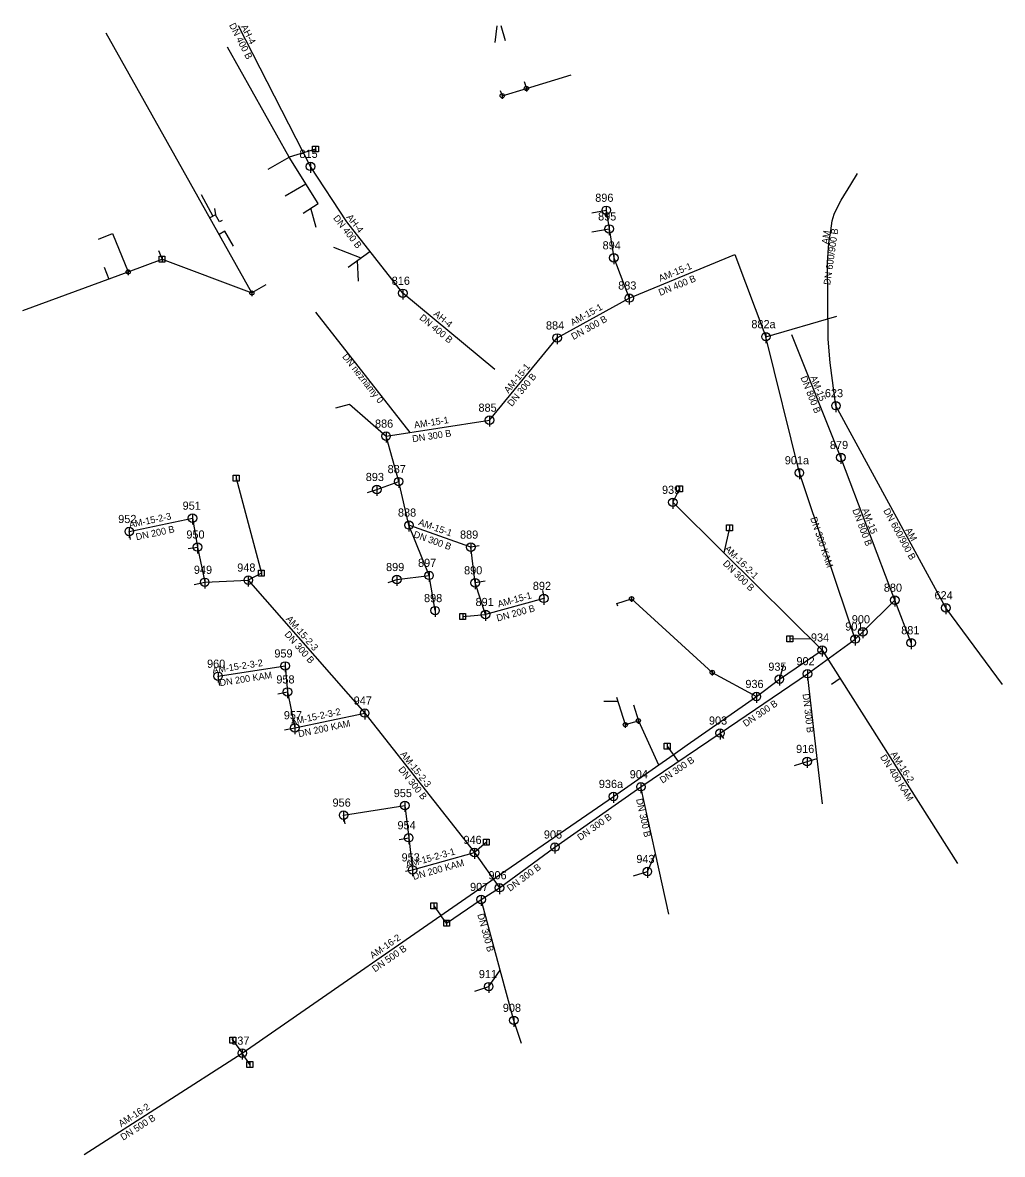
# Model space of a CAD drawing. Extents: x -492400 to -492169, y -1127087 to -1126820.
import ezdxf

# ---------------------------------------------------------------- set-up
doc = ezdxf.new("R2010")
doc.units = 0
for name, color, linetype in [('_pripojka_kanal_destova_priblizne_', 7, 'Continuous'), ('_pripojka_kanal_jednotna_prevzato_z_dokumentace_', 7, 'Continuous'), ('_pripojka_kanal_jednotna_priblizne_', 7, 'Continuous'), ('_pripojka_kanal_splaskova_priblizne_', 7, 'Continuous'), ('_stoka_jednotna_smvak_prevzato_z_dokumentace_', 7, 'Continuous'), ('_stoka_jednotna_smvak_priblizne_', 7, 'Continuous'), ('Default', 7, 'Continuous'), ('MoLevel 1', 7, 'Continuous'), ('MoLevel 119', 7, 'Continuous'), ('MoLevel 120', 7, 'Continuous'), ('MoLevel 2', 7, 'Continuous'), ('MoLevel 57', 7, 'Continuous'), ('MoLevel 60', 7, 'Continuous'), ('MoLevel 63', 7, 'Continuous'), ('MoLevel 68', 7, 'Continuous'), ('MoLevel 69', 7, 'Continuous')]:
    doc.layers.add(name, color=color, linetype=linetype)

# ---------------------------------------------------------------- blocks, each defined once
blk = doc.blocks.new('_vpust_')
at = {"layer": 'Default'}
blk.add_line((0, 0.000025), (0, -0.000025), dxfattribs=at)
blk.add_lwpolyline([(-0.000035, 0.000035), (0.000035, 0.000035), (0.000035, -0.000035), (-0.000035, -0.000035), (-0.000035, 0.000035)], dxfattribs=at)
blk = doc.blocks.new('_sachta_kanal_prip_')
at = {"layer": 'Default'}
blk.add_line((0, 0.00005), (0, -0.000075), dxfattribs=at)
blk.add_circle((0, 0), 0.00005, dxfattribs=at)
blk = doc.blocks.new('_sachta_kanal_prevzato_z_dokumentace_')
at = {"layer": 'Default'}
blk.add_line((0, 0.00005), (0, -0.000075), dxfattribs=at)
blk.add_circle((0, 0), 0.00005, dxfattribs=at)

msp = doc.modelspace()

# ---------------------------------------------------------------- linework, layer by layer
at = {"layer": '_pripojka_kanal_destova_priblizne_'}
for p, q in [((-492345.92, -1126883.53), (-492380.35, -1126822.11)), ((-492288.43, -1126824.33), (-492288, -1126820.38)), ((-492342.1, -1126854.29), (-492337.11, -1126851.45)), ((-492330.86, -1126849.51), (-492337.11, -1126851.45)), ((-492338.06, -1126860.58), (-492333.15, -1126857.76)), ((-492357.85, -1126860.28), (-492355.15, -1126865.41)), ((-492353.53, -1126866.74), (-492354.49, -1126865.04)), ((-492330.74, -1126868.06), (-492332.01, -1126863.53)), ((-492352.9, -1126866.39), (-492353.53, -1126866.74)), ((-492326.6, -1126872.68), (-492320.16, -1126875.26)), ((-492375.13, -1126878.56), (-492367.14, -1126875.52)), ((-492367.95, -1126873.53), (-492367.14, -1126875.52)), ((-492367.14, -1126875.52), (-492345.92, -1126883.53)), ((-492323.14, -1126877.45), (-492318.02, -1126873.7)), ((-492380.81, -1126877.47), (-492379.72, -1126880.25)), ((-492320.73, -1126880.78), (-492320.95, -1126875.84)), ((-492400.05, -1126887.71), (-492375.13, -1126878.56)), ((-492342.59, -1126881.61), (-492345.92, -1126883.53)), ((-492349.62, -1126927.31), (-492343.67, -1126949.76)), ((-492244.91, -1126929.83), (-492246.47, -1126933.01)), ((-492233.11, -1126939.05), (-492234.4, -1126944.95)), ((-492343.67, -1126949.76), (-492346.75, -1126951.39)), ((-492256.22, -1126955.79), (-492237.18, -1126973.21)), ((-492296.12, -1126959.98), (-492290.74, -1126959.51)), ((-492218.82, -1126965.25), (-492213.92, -1126965.22)), ((-492220.38, -1126971.34), (-492221.32, -1126974.81)), ((-492237.18, -1126973.21), (-492226.74, -1126978.9)), ((-492262.81, -1126980.03), (-492259.45, -1126980.04)), ((-492234.44, -1126988.81), (-492235.34, -1126987.54)), ((-492247.81, -1126990.64), (-492245.25, -1126994.28)), ((-492290.53, -1127013.33), (-492293.33, -1127015.75)), ((-492299.91, -1127032.48), (-492291.76, -1127026.86)), ((-492302.92, -1127028.36), (-492301.25, -1127030.63)), ((-492299.91, -1127032.48), (-492301.25, -1127030.63)), ((-492350.41, -1127060.13), (-492348.18, -1127063.19)), ((-492346.42, -1127065.89), (-492348.18, -1127063.19))]:
    msp.add_line(p, q, dxfattribs=at)
for points in [[(-492354.72, -1126863.58), (-492354.49, -1126865.04), (-492355.86, -1126865.8)], [(-492382.13, -1126870.8), (-492378.83, -1126869.49), (-492375.13, -1126878.56)], [(-492350.26, -1126872.5), (-492352.28, -1126868.94), (-492353.67, -1126869.7)], [(-492259.51, -1126957.55), (-492259.7, -1126956.95), (-492256.22, -1126955.79)]]:
    msp.add_lwpolyline(points, dxfattribs=at)
at = {"layer": '_pripojka_kanal_jednotna_prevzato_z_dokumentace_'}
for p, q in [((-492265.61, -1126864.62), (-492262.2, -1126863.99)), ((-492265.62, -1126869.1), (-492261.53, -1126868.4)), ((-492318.59, -1126930.71), (-492316.4, -1126929.98)), ((-492374.55, -1126941.78), (-492374.87, -1126939.91)), ((-492360.97, -1126943.93), (-492358.77, -1126943.57)), ((-492292.22, -1126943.28), (-492294.19, -1126943.6)), ((-492359.55, -1126952.39), (-492357.04, -1126951.91)), ((-492313.71, -1126951.95), (-492311.66, -1126951.26)), ((-492290.82, -1126951.64), (-492293.18, -1126952.04)), ((-492277.23, -1126953.82), (-492276.89, -1126955.75)), ((-492353.5, -1126976.27), (-492353.89, -1126974.11)), ((-492339.77, -1126978.24), (-492337.51, -1126977.82)), ((-492338.23, -1126986.75), (-492335.75, -1126986.29)), ((-492217.71, -1126995.22), (-492214.76, -1126994.25)), ((-492323.89, -1127008.99), (-492324.25, -1127006.93)), ((-492311.1, -1127012.7), (-492308.86, -1127012.28)), ((-492309.59, -1127020.14), (-492307.94, -1127019.88)), ((-492255.77, -1127021.31), (-492252.49, -1127020.25)), ((-492293.24, -1127048.54), (-492289.97, -1127047.45))]:
    msp.add_line(p, q, dxfattribs=at)
at = {"layer": '_pripojka_kanal_jednotna_priblizne_'}
for p, q in [((-492285.97, -1126823.95), (-492287.02, -1126820.38)), ((-492337.11, -1126851.45), (-492351.7, -1126825.46)), ((-492281.06, -1126835.2), (-492270.5, -1126831.98)), ((-492286.77, -1126836.93), (-492281.06, -1126835.2)), ((-492281.59, -1126833.58), (-492281.06, -1126835.2)), ((-492287.25, -1126835.68), (-492286.77, -1126836.93)), ((-492330.23, -1126862.41), (-492337.11, -1126851.45)), ((-492333.79, -1126864.66), (-492330.23, -1126862.41)), ((-492326.05, -1126910.67), (-492322.88, -1126909.84)), ((-492259.76, -1126979.07), (-492257.71, -1126985.55)), ((-492257.71, -1126985.55), (-492254.63, -1126984.63)), ((-492254.63, -1126984.63), (-492249.84, -1126995.05))]:
    msp.add_line(p, q, dxfattribs=at)
at = {"layer": '_pripojka_kanal_splaskova_priblizne_'}
for p, q in [((-492330.91, -1126888.04), (-492308.63, -1126916.51)), ((-492208.99, -1126975.99), (-492206.98, -1126974.58)), ((-492255.78, -1126980.85), (-492254.63, -1126984.63))]:
    msp.add_line(p, q, dxfattribs=at)
at = {"layer": '_stoka_jednotna_smvak_prevzato_z_dokumentace_'}
for p, q in [((-492332.06, -1126853.61), (-492349.05, -1126820.38)), ((-492262.2, -1126863.99), (-492261.53, -1126868.4)), ((-492261.53, -1126868.4), (-492260.41, -1126875.23)), ((-492260.41, -1126875.23), (-492256.77, -1126884.73)), ((-492256.77, -1126884.73), (-492231.86, -1126874.46)), ((-492273.79, -1126894.16), (-492256.77, -1126884.73)), ((-492289.78, -1126913.6), (-492273.79, -1126894.16)), ((-492216.6, -1126926.03), (-492224.49, -1126893.86)), ((-492206.81, -1126922.42), (-492218.35, -1126893.4)), ((-492182.01, -1126957.94), (-492207.96, -1126910.17)), ((-492314.22, -1126917.37), (-492289.78, -1126913.6)), ((-492311.24, -1126928.11), (-492314.22, -1126917.37)), ((-492194.04, -1126956.14), (-492206.81, -1126922.42)), ((-492203.42, -1126965.32), (-492216.6, -1126926.03)), ((-492316.4, -1126929.98), (-492311.24, -1126928.11)), ((-492308.8, -1126938.39), (-492311.24, -1126928.11)), ((-492374.87, -1126939.91), (-492359.93, -1126936.76)), ((-492359.93, -1126936.76), (-492358.77, -1126943.57)), ((-492294.19, -1126943.6), (-492308.8, -1126938.39)), ((-492304.06, -1126950.27), (-492308.8, -1126938.39)), ((-492358.77, -1126943.57), (-492357.04, -1126951.91)), ((-492293.18, -1126952.04), (-492294.19, -1126943.6)), ((-492311.66, -1126951.26), (-492304.06, -1126950.27)), ((-492302.64, -1126958.6), (-492304.06, -1126950.27)), ((-492357.04, -1126951.91), (-492346.75, -1126951.39)), ((-492346.75, -1126951.39), (-492319.26, -1126982.82)), ((-492290.74, -1126959.52), (-492293.18, -1126952.04)), ((-492276.94, -1126955.72), (-492290.74, -1126959.52)), ((-492201.6, -1126963.61), (-492194.04, -1126956.14)), ((-492190.2, -1126966.19), (-492194.04, -1126956.14)), ((-492168.65, -1126976.03), (-492182.01, -1126957.94)), ((-492203.42, -1126965.32), (-492201.6, -1126963.61)), ((-492214.68, -1126973.51), (-492203.42, -1126965.32)), ((-492221.32, -1126974.81), (-492211.2, -1126967.91)), ((-492211.2, -1126967.91), (-492179.25, -1127018.37)), ((-492353.89, -1126974.11), (-492338.04, -1126971.68)), ((-492338.04, -1126971.68), (-492337.51, -1126977.82)), ((-492235.34, -1126987.54), (-492214.68, -1126973.51)), ((-492212.39, -1126993.52), (-492214.68, -1126973.51)), ((-492226.74, -1126978.9), (-492221.32, -1126974.81)), ((-492337.51, -1126977.82), (-492335.75, -1126986.29)), ((-492243.1, -1126990.34), (-492226.74, -1126978.9)), ((-492335.75, -1126986.29), (-492319.26, -1126982.82)), ((-492319.26, -1126982.82), (-492293.33, -1127015.75)), ((-492254.01, -1127000.23), (-492235.34, -1126987.54)), ((-492246.43, -1126992.67), (-492243.1, -1126990.34)), ((-492260.52, -1127002.52), (-492246.43, -1126992.67)), ((-492214.76, -1126994.25), (-492212.39, -1126993.52)), ((-492211.17, -1127004.23), (-492212.39, -1126993.52)), ((-492274.33, -1127014.47), (-492254.01, -1127000.23)), ((-492250.54, -1127016.01), (-492254.01, -1127000.23)), ((-492324.25, -1127006.93), (-492309.79, -1127004.67)), ((-492309.79, -1127004.67), (-492308.86, -1127012.28)), ((-492308.86, -1127012.28), (-492307.94, -1127019.88)), ((-492287.43, -1127024.09), (-492274.33, -1127014.47)), ((-492307.94, -1127019.88), (-492293.33, -1127015.75)), ((-492293.33, -1127015.75), (-492287.43, -1127024.09)), ((-492252.49, -1127020.25), (-492250.54, -1127016.01)), ((-492247.4, -1127030.36), (-492250.54, -1127016.01)), ((-492291.76, -1127026.86), (-492287.43, -1127024.09)), ((-492287.24, -1127043.56), (-492291.76, -1127026.86)), ((-492289.97, -1127047.45), (-492287.25, -1127043.57)), ((-492284.03, -1127055.43), (-492287.24, -1127043.56)), ((-492282.24, -1127060.93), (-492284.03, -1127055.43)), ((-492385.56, -1127087.1), (-492348.18, -1127063.19))]:
    msp.add_line(p, q, dxfattribs=at)
for points in [[(-492310.26, -1126883.61), (-492323.46, -1126866.73), (-492332.06, -1126853.61)], [(-492246.47, -1126933.01), (-492234.4, -1126944.95), (-492211.2, -1126967.91)], [(-492348.18, -1127063.19), (-492288.46, -1127021.76), (-492260.52, -1127002.52)]]:
    msp.add_lwpolyline(points, dxfattribs=at)
at = {"layer": '_stoka_jednotna_smvak_priblizne_'}
for p, q in [((-492231.86, -1126874.46), (-492224.49, -1126893.86)), ((-492288.5, -1126901.6), (-492310.26, -1126883.61)), ((-492224.49, -1126893.86), (-492207.77, -1126888.98)), ((-492322.88, -1126909.84), (-492314.22, -1126917.37))]:
    msp.add_line(p, q, dxfattribs=at)
msp.add_lwpolyline([(-492207.96, -1126910.17), (-492209.3, -1126900.01), (-492209.77, -1126894.44), (-492209.94, -1126876.36), (-492209.61, -1126871.75), (-492209.19, -1126868.85), (-492208.87, -1126866.47), (-492208.35, -1126864.92), (-492208, -1126864.02), (-492206.71, -1126861.61), (-492204.45, -1126857.92), (-492202.88, -1126855.26)], dxfattribs=at)

# ---------------------------------------------------------------- block references
at = {"layer": 'MoLevel 119', "xscale": 20000, "yscale": 20000}
for p in [(-492332.06, -1126853.61), (-492262.2, -1126863.99), (-492261.53, -1126868.4), (-492260.41, -1126875.23), (-492310.26, -1126883.61), (-492256.77, -1126884.73), (-492273.79, -1126894.16), (-492224.49, -1126893.86), (-492207.96, -1126910.17), (-492289.78, -1126913.6), (-492314.22, -1126917.37), (-492206.81, -1126922.42), (-492216.6, -1126926.03), (-492316.4, -1126929.98), (-492311.24, -1126928.11), (-492246.47, -1126933.01), (-492359.93, -1126936.76), (-492374.87, -1126939.91), (-492308.8, -1126938.39), (-492358.77, -1126943.57), (-492294.19, -1126943.6), (-492346.75, -1126951.39), (-492311.66, -1126951.26), (-492304.06, -1126950.27), (-492357.04, -1126951.91), (-492293.18, -1126952.04), (-492276.94, -1126955.72), (-492194.04, -1126956.14), (-492302.64, -1126958.6), (-492290.74, -1126959.52), (-492182.01, -1126957.94), (-492201.6, -1126963.61), (-492203.42, -1126965.32), (-492190.2, -1126966.19), (-492211.2, -1126967.91), (-492338.04, -1126971.68), (-492353.89, -1126974.11), (-492221.32, -1126974.81), (-492214.68, -1126973.51), (-492337.51, -1126977.82), (-492226.74, -1126978.9), (-492319.26, -1126982.82), (-492335.75, -1126986.29), (-492235.34, -1126987.54), (-492214.76, -1126994.25), (-492254.01, -1127000.23), (-492309.79, -1127004.67), (-492260.52, -1127002.52), (-492324.25, -1127006.93), (-492308.86, -1127012.28), (-492293.33, -1127015.75), (-492274.33, -1127014.47), (-492307.94, -1127019.88), (-492252.49, -1127020.25), (-492287.43, -1127024.09), (-492291.76, -1127026.86), (-492289.97, -1127047.45), (-492284.03, -1127055.43), (-492348.18, -1127063.19)]:
    msp.add_blockref('_sachta_kanal_prevzato_z_dokumentace_', p, dxfattribs=at)
at = {"layer": 'MoLevel 57', "xscale": 10000, "yscale": 10000}
for p in [(-492281.06, -1126835.2), (-492286.77, -1126836.93), (-492375.13, -1126878.56), (-492345.92, -1126883.53), (-492256.22, -1126955.79), (-492237.18, -1126973.21), (-492257.71, -1126985.55), (-492254.63, -1126984.63)]:
    msp.add_blockref('_sachta_kanal_prip_', p, dxfattribs=at)
at = {"layer": 'MoLevel 63', "xscale": 20000, "yscale": 20000}
for p in [(-492330.86, -1126849.51), (-492367.14, -1126875.52), (-492349.62, -1126927.31), (-492244.91, -1126929.83), (-492233.11, -1126939.05), (-492343.67, -1126949.76), (-492296.12, -1126959.98), (-492218.82, -1126965.25), (-492247.81, -1126990.64), (-492290.53, -1127013.33), (-492302.92, -1127028.36), (-492299.91, -1127032.48), (-492350.41, -1127060.13), (-492346.42, -1127065.89)]:
    msp.add_blockref('_vpust_', p, dxfattribs=at)

# ---------------------------------------------------------------- texts
at = {"layer": 'MoLevel 1'}
for s, height, rotation, p in [('DN 600/900 B', 1.6049, 81.7674, (-492209.32, -1126881.74)), ('DN 400 B', 1.605, 320.4161, (-492306.48, -1126889.62))]:
    msp.add_text(s, height=height, rotation=rotation, dxfattribs=at).set_placement(p)
at = {"layer": 'MoLevel 120'}
for s, p in [('815', (-492334.67, -1126851.61)), ('896', (-492264.81, -1126861.99)), ('895', (-492264.14, -1126866.4)), ('894', (-492263.07, -1126873.23)), ('816', (-492312.88, -1126881.61)), ('883', (-492259.39, -1126882.73)), ('884', (-492276.45, -1126892.16)), ('882a', (-492227.93, -1126891.86)), ('623', (-492210.57, -1126908.17)), ('885', (-492292.39, -1126911.6)), ('886', (-492316.83, -1126915.37)), ('879', (-492209.38, -1126920.42)), ('901a', (-492220.04, -1126924.03)), ('893', (-492319.01, -1126927.98)), ('887', (-492313.85, -1126926.11)), ('939', (-492249.04, -1126931.01)), ('951', (-492362.27, -1126934.76)), ('888', (-492311.41, -1126936.39)), ('952', (-492377.48, -1126937.91)), ('950', (-492361.38, -1126941.57)), ('889', (-492296.75, -1126941.6)), ('949', (-492359.61, -1126949.91)), ('948', (-492349.37, -1126949.39)), ('899', (-492314.22, -1126949.26)), ('897', (-492306.67, -1126948.27)), ('890', (-492295.79, -1126950.04)), ('892', (-492279.55, -1126953.72)), ('880', (-492196.65, -1126954.14)), ('898', (-492305.25, -1126956.6)), ('891', (-492293.08, -1126957.52)), ('624', (-492184.67, -1126955.94)), ('900', (-492204.21, -1126961.61)), ('934', (-492213.86, -1126965.91)), ('901', (-492205.76, -1126963.32)), ('881', (-492192.54, -1126964.19)), ('959', (-492340.6, -1126969.68)), ('960', (-492356.5, -1126972.11)), ('935', (-492223.93, -1126972.81)), ('902', (-492217.29, -1126971.51)), ('958', (-492340.13, -1126975.82)), ('936', (-492229.35, -1126976.9)), ('947', (-492321.87, -1126980.82)), ('957', (-492338.36, -1126984.29)), ('903', (-492237.95, -1126985.54)), ('916', (-492217.37, -1126992.25)), ('936a', (-492263.96, -1127000.52)), ('904', (-492256.67, -1126998.23)), ('955', (-492312.41, -1127002.67)), ('956', (-492326.86, -1127004.93)), ('954', (-492311.52, -1127010.28)), ('946', (-492295.94, -1127013.75)), ('905', (-492276.94, -1127012.47)), ('953', (-492310.55, -1127017.88)), ('943', (-492255.1, -1127018.25)), ('906', (-492290.04, -1127022.09)), ('907', (-492294.38, -1127024.86)), ('911', (-492292.3, -1127045.45)), ('908', (-492286.64, -1127053.43)), ('937', (-492350.79, -1127061.19))]:
    msp.add_text(s, height=1.926, dxfattribs=at).set_placement(p)
at = {"layer": 'MoLevel 2'}
for s, rotation, p in [('AM', 81.7674, (-492209.78, -1126872.08)), ('AH-4', 320.4161, (-492303.13, -1126888.71)), ('AH-4', 320.4161, (-492303.13, -1126888.71)), ('AH-4', 320.4161, (-492303.13, -1126888.71))]:
    msp.add_text(s, height=1.605, rotation=rotation, dxfattribs=at).set_placement(p)
at = {"layer": 'MoLevel 60'}
msp.add_text('DN neznámý 0', height=1.6049, rotation=308.0485, dxfattribs=at).set_placement((-492324.67, -1126898.62))
at = {"layer": 'MoLevel 68'}
for s, height, rotation, p in [('DN 400 B', 1.605, 297.0916, (-492351.35, -1126820.22)), ('DN 400 B', 1.605, 308.0267, (-492326.8, -1126865.87)), ('DN 400 B', 1.605, 22.4237, (-492249.46, -1126884.25)), ('DN 300 B', 1.605, 28.9931, (-492269.95, -1126894.67)), ('DN 300 B', 1.605, 50.5556, (-492284.5, -1126910.51)), ('DN 800 B', 1.605, 291.6897, (-492216.37, -1126903.52)), ('DN 300 B', 1.605, 8.7782, (-492307.91, -1126918.82)), ('DN 800 B', 1.605, 290.7454, (-492204.13, -1126934.82)), ('DN 600/900 B', 1.6049, 298.512, (-492196.83, -1126934.96)), ('DN 300 KAM', 1.605, 288.5501, (-492214.05, -1126936.76)), ('DN 200 B', 1.605, 11.9194, (-492373.16, -1126941.99)), ('DN 300 B', 1.605, 340.3959, (-492307.9, -1126941.22)), ('DN 300 B', 1.605, 315.2979, (-492234.78, -1126947.63)), ('DN 200 B', 1.605, 15.3756, (-492287.88, -1126961.19)), ('DN 300 B', 1.605, 311.1821, (-492338.32, -1126964.28)), ('DN 200 KAM', 1.605, 8.7182, (-492353.42, -1126976.46)), ('DN 300 B', 1.605, 34.1794, (-492229.26, -1126986.15)), ('DN 300 B', 1.605, 276.5095, (-492215.84, -1126978.31)), ('DN 200 KAM', 1.605, 11.8941, (-492334.8, -1126988.53)), ('DN 300 B', 1.605, 34.2186, (-492248.92, -1126999.51)), ('DN 400 KAM', 1.605, 302.341, (-492197.58, -1126993.23)), ('DN 300 B', 1.605, 308.2209, (-492311.41, -1126996.18)), ('DN 300 B', 1.605, 282.3707, (-492255.18, -1127003.18)), ('DN 300 B', 1.605, 35.0176, (-492268.35, -1127013.04)), ('DN 200 KAM', 1.605, 15.7966, (-492307.7, -1127022.28)), ('DN 300 B', 1.605, 36.2972, (-492284.95, -1127025.06)), ('DN 300 B', 1.605, 285.1404, (-492292.68, -1127030.42)), ('DN 500 B', 1.605, 34.7522, (-492316.83, -1127044.12)), ('DN 500 B', 1.605, 32.605, (-492376.32, -1127083.9))]:
    msp.add_text(s, height=height, rotation=rotation, dxfattribs=at).set_placement(p)
at = {"layer": 'MoLevel 69'}
for s, height, rotation, p in [('AH-4', 1.605, 297.0916, (-492348.55, -1126820.58)), ('AH-4', 1.605, 308.0267, (-492323.67, -1126865.66)), ('AM-15-1', 1.605, 22.4237, (-492249.44, -1126880.91)), ('AM-15-1', 1.605, 28.9931, (-492270.13, -1126891.33)), ('AM-15-1', 1.605, 50.5556, (-492285.3, -1126907.36)), ('AM-15', 1.605, 291.6897, (-492214.06, -1126903.39)), ('AM-15-1', 1.605, 8.7782, (-492307.48, -1126915.53)), ('AM-15-2-3', 1.605, 11.9194, (-492374.76, -1126939.09)), ('AM-15-1', 1.605, 340.3959, (-492306.71, -1126938.34)), ('AM-15', 1.605, 290.7454, (-492201.84, -1126934.73)), ('AM', 1.605, 298.512, (-492191.65, -1126939.54)), ('AM-16-2-1', 1.605, 315.2979, (-492234.41, -1126944.14)), ('AM-15-1', 1.605, 15.3756, (-492287.64, -1126957.86)), ('AM-15-2-3', 1.605, 311.1821, (-492337.96, -1126960.64)), ('AM-15-2-3-2', 1.6049, 8.7182, (-492355.14, -1126973.5)), ('AM-15-2-3-2', 1.6049, 11.8941, (-492336.59, -1126985.67)), ('AM-15-2-3', 1.605, 308.2209, (-492310.95, -1126992.57)), ('AM-16-2', 1.605, 302.341, (-492195.14, -1126992.48)), ('AM-15-2-3-1', 1.6049, 15.7966, (-492309.35, -1127019.48)), ('AM-16-2', 1.605, 34.7522, (-492317.37, -1127040.94)), ('AM-16-2', 1.605, 32.605, (-492376.79, -1127080.7))]:
    msp.add_text(s, height=height, rotation=rotation, dxfattribs=at).set_placement(p)

doc.saveas('drawing.dxf')
